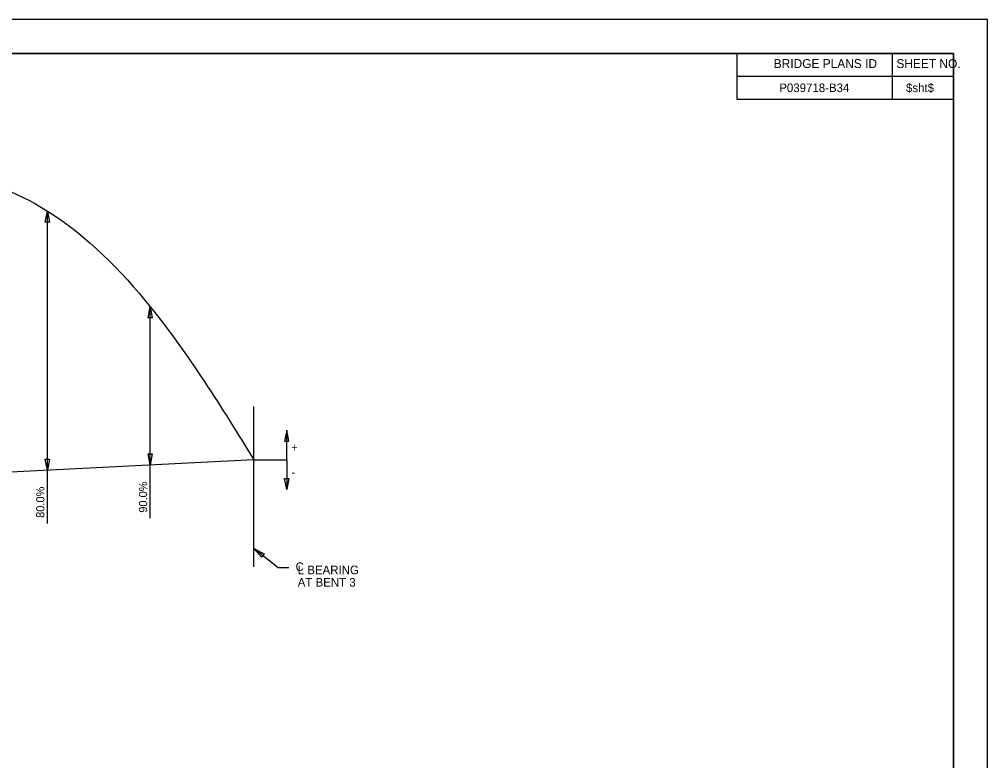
# Model space of a CAD drawing. Extents: x -125.5 to -89.4, y -5.1 to 16.9.
# Drawn here: x -103.66 to -89.53, y 6.12 to 16.93 of the extents above; entities that cross this region are included whole.
import ezdxf

# ---------------------------------------------------------------- set-up
doc = ezdxf.new("R2010")
doc.units = 0
for name, color, linetype in [('BR_AUTO DIMENSION', 7, 'Continuous'), ('BR_BORDER LINES', 7, 'Continuous'), ('BR_CENTER LINES', 7, 'Continuous'), ('BR_TABLE LINES', 7, 'Continuous'), ('BR_TEXT', 7, 'Continuous'), ('Level 31', 7, 'Continuous')]:
    doc.layers.add(name, color=color, linetype=linetype)

msp = doc.modelspace()

# ---------------------------------------------------------------- linework, layer by layer
at = {"layer": 'BR_AUTO DIMENSION'}
for p, q in [((-100.24, 10.507), (-99.76, 10.507)), ((-99.888, 8.933), (-100.24, 9.213)), ((-99.728, 8.933), (-99.888, 8.933))]:
    msp.add_line(p, q, dxfattribs=at)
for points in [[(-103.285, 13.974), (-103.253, 14.137), (-103.222, 13.974)], [(-101.785, 12.579), (-101.753, 12.742), (-101.722, 12.579)], [(-99.728, 10.778), (-99.76, 10.941), (-99.791, 10.778)], [(-103.222, 10.519), (-103.253, 10.357), (-103.285, 10.519)], [(-101.722, 10.594), (-101.753, 10.432), (-101.785, 10.594)], [(-99.728, 10.237), (-99.76, 10.074), (-99.791, 10.237)], [(-100.131, 9.089), (-100.24, 9.213), (-100.092, 9.138)]]:
    msp.add_lwpolyline(points, close=True, dxfattribs=at)
at = {"layer": 'BR_BORDER LINES'}
for p, q in [((-90.033, 16.434), (-123.699, 16.434)), ((-93.186, 15.767), (-93.186, 16.434)), ((-90.919, 15.767), (-90.919, 16.434)), ((-90.033, -4.566), (-90.033, 16.434)), ((-93.186, 16.104), (-90.033, 16.104)), ((-90.919, 16.104), (-90.033, 16.104)), ((-90.033, 15.767), (-93.186, 15.767))]:
    msp.add_line(p, q, dxfattribs=at)
at = {"layer": 'BR_CENTER LINES'}
msp.add_line((-100.24, 8.946), (-100.24, 11.285), dxfattribs=at)
at = {"layer": 'BR_TABLE LINES'}
for p, q in [((-103.253, 9.581), (-103.253, 14.137)), ((-101.753, 9.656), (-101.753, 12.742)), ((-99.76, 10.507), (-99.76, 10.941)), ((-100.24, 10.507), (-115.253, 9.757)), ((-99.76, 10.507), (-99.76, 10.074))]:
    msp.add_line(p, q, dxfattribs=at)
msp.add_lwpolyline([(-123.699, 16.434), (-90.033, 16.434), (-90.033, -4.566), (-123.699, -4.566)], close=True, dxfattribs=at)
msp.add_spline([(-115.253, 9.757), (-113.753, 10.237), (-112.253, 10.957), (-110.753, 11.827), (-110.048, 12.237), (-109.253, 12.712), (-107.753, 13.552), (-106.253, 14.272), (-104.753, 14.647), (-103.253, 14.137), (-101.753, 12.742), (-100.24, 10.507)], degree=3, dxfattribs=at)
at = {"layer": 'Level 31'}
msp.add_line((-89.533, 16.934), (-125.533, 16.934), dxfattribs=at)
msp.add_lwpolyline([(-125.533, 16.934), (-125.533, -5.066), (-89.533, -5.066), (-89.533, 16.934)], dxfattribs=at)

# ---------------------------------------------------------------- texts
at = {"layer": 'BR_AUTO DIMENSION'}
for s, p in [('C', (-99.632, 8.885)), ('L BEARING', (-99.6, 8.839)), ('AT BENT 3', (-99.6, 8.658))]:
    msp.add_text(s, height=0.125, dxfattribs=at).set_placement(p)
at = {"layer": 'BR_TEXT'}
for s, height, p in [('BRIDGE PLANS ID', 0.13, (-92.654, 16.224)), ('SHEET NO.', 0.13, (-90.864, 16.224)), ('P039718-B34', 0.125, (-92.573, 15.873)), ('$sht$', 0.125, (-90.724, 15.873)), ('-', 0.12, (-99.689, 10.267))]:
    msp.add_text(s, height=height, dxfattribs=at).set_placement(p)
for s, rotation, p in [('+', 360, (-99.698, 10.628)), ('90.0%', 90, (-101.797, 9.736)), ('80.0%', 90, (-103.297, 9.661))]:
    msp.add_text(s, height=0.12, rotation=rotation, dxfattribs=at).set_placement(p)

doc.saveas('drawing.dxf')
